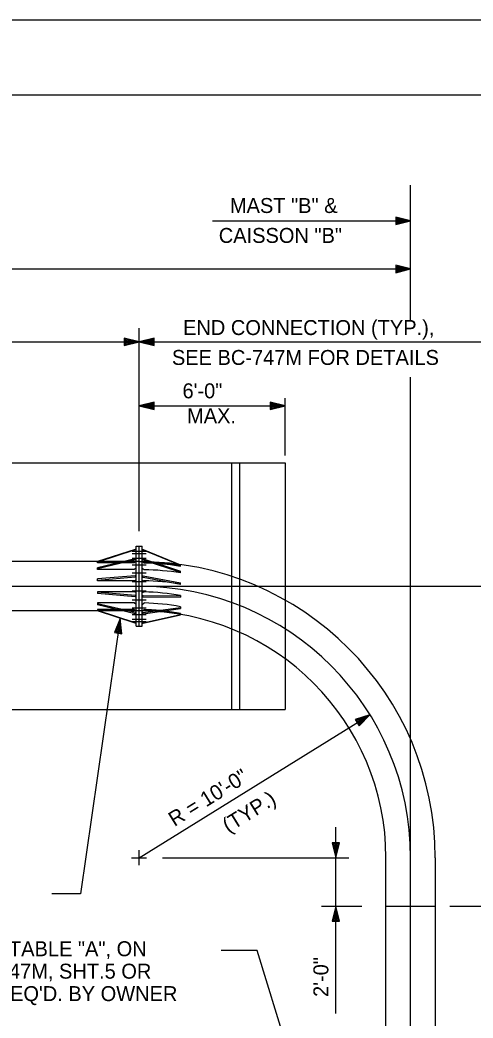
# Model space of a CAD drawing. Extents: x 640117 to 642655, y 297247 to 298435.
# Drawn here: x 641584 to 641674.8, y 298235.3 to 298435.5 of the extents above; entities that cross this region are included whole.
import ezdxf

# ---------------------------------------------------------------- set-up
doc = ezdxf.new("R2010")
doc.units = 0
for name, color, linetype in [('2', 7, 'Continuous'), ('48', 7, 'Continuous'), ('49', 7, 'Continuous'), ('50', 7, 'Continuous'), ('52', 7, 'Continuous'), ('53', 7, 'Continuous'), ('55', 7, 'Continuous'), ('PLT-BNDY', 7, 'Continuous')]:
    doc.layers.add(name, color=color, linetype=linetype)

msp = doc.modelspace()

# ---------------------------------------------------------------- linework, layer by layer
at = {"layer": '2'}
msp.add_line((640998.46, 298420.46), (641784.46, 298420.46), dxfattribs=at)
at = {"layer": '48'}
for p, q in [((641606.53, 298328.95), (641609.3, 298328.95)), ((641606.53, 298328.47), (641609.3, 298328.47)), ((641606.53, 298327.54), (641609.3, 298327.54)), ((641606.53, 298326.23), (641609.3, 298326.23)), ((641606.53, 298324.62), (641609.3, 298324.62)), ((641606.53, 298322.83), (641609.3, 298322.83)), ((641606.53, 298320.97), (641609.3, 298320.97)), ((641606.53, 298319.18), (641609.3, 298319.18)), ((641606.53, 298317.57), (641609.3, 298317.57)), ((641606.53, 298316.25), (641609.3, 298316.25)), ((641606.53, 298315.33), (641609.3, 298315.33)), ((641606.53, 298314.85), (641609.3, 298314.85))]:
    msp.add_line(p, q, dxfattribs=at)
at = {"layer": '49'}
for p, q in [((641573.28, 298346.63), (641637.17, 298346.63)), ((641626.4, 298346.63), (641626.4, 298297.16)), ((641628.05, 298346.63), (641628.05, 298297.16)), ((641637.17, 298346.63), (641637.17, 298297.16)), ((641573.28, 298297.16), (641637.17, 298297.16))]:
    msp.add_line(p, q, dxfattribs=at)
at = {"layer": '50'}
for p, q in [((641662.33, 298375.25), (641662.33, 298402.36)), ((641662.33, 298166.4), (641662.33, 298363.86)), ((641032.47, 298321.9), (641730.35, 298321.9))]:
    msp.add_line(p, q, dxfattribs=at)
msp.add_arc((641607.91, 298267.48), 54.42, 0, 90, dxfattribs=at)
at = {"layer": '52'}
for p, q in [((641622.6, 298395.18), (641662.33, 298395.18)), ((641286.35, 298385.52), (641662.33, 298385.52)), ((641662.33, 298385.52), (641659.33, 298386.27)), ((641659.33, 298386.27), (641659.33, 298384.77)), ((641659.33, 298384.77), (641662.33, 298385.52)), ((641661.6, 298385.52), (641659.51, 298386.04)), ((641659.51, 298386.04), (641659.51, 298385)), ((641659.51, 298385), (641661.6, 298385.52)), ((641660.86, 298385.52), (641659.68, 298385.81)), ((641659.68, 298385.81), (641659.68, 298385.22)), ((641659.68, 298385.22), (641660.86, 298385.52)), ((641659.75, 298385.43), (641660.13, 298385.52)), ((641660.13, 298385.52), (641659.77, 298385.61)), ((641607.91, 298332.93), (641607.91, 298373.65)), ((641607.91, 298370.91), (641604.91, 298371.66)), ((641604.91, 298371.66), (641604.91, 298370.16)), ((641604.91, 298370.16), (641607.91, 298370.91)), ((641607.18, 298370.91), (641605.09, 298371.44)), ((641605.09, 298371.44), (641605.09, 298370.39)), ((641605.09, 298370.39), (641607.18, 298370.91)), ((641606.45, 298370.91), (641605.27, 298371.21)), ((641605.27, 298371.21), (641605.27, 298370.62)), ((641605.27, 298370.62), (641606.45, 298370.91)), ((641605.34, 298370.82), (641605.71, 298370.91)), ((641605.71, 298370.91), (641605.36, 298371)), ((641610.91, 298371.66), (641607.91, 298370.91)), ((641607.91, 298370.91), (641610.91, 298370.16)), ((641610.73, 298371.44), (641608.64, 298370.91)), ((641608.64, 298370.91), (641610.73, 298370.39)), ((641610.56, 298371.21), (641609.38, 298370.91)), ((641609.38, 298370.91), (641610.56, 298370.62)), ((641610.49, 298371.01), (641610.11, 298370.91)), ((641610.11, 298370.91), (641610.47, 298370.82)), ((641610.56, 298370.62), (641610.56, 298371.21)), ((641610.73, 298370.39), (641610.73, 298371.44)), ((641610.91, 298370.16), (641610.91, 298371.66)), ((641610.91, 298358.84), (641607.91, 298358.09)), ((641610.91, 298357.34), (641610.91, 298358.84)), ((641637.17, 298358.09), (641634.17, 298358.84)), ((641634.17, 298358.84), (641634.17, 298357.34)), ((641637.17, 298348.13), (641637.17, 298359.59)), ((641607.91, 298358.09), (641637.17, 298358.09)), ((641607.91, 298358.09), (641610.91, 298357.34)), ((641610.73, 298358.61), (641608.64, 298358.09)), ((641608.64, 298358.09), (641610.73, 298357.57)), ((641610.56, 298358.39), (641609.38, 298358.09)), ((641609.38, 298358.09), (641610.56, 298357.8)), ((641610.49, 298358.18), (641610.11, 298358.09)), ((641610.11, 298358.09), (641610.47, 298358)), ((641610.56, 298357.8), (641610.56, 298358.39)), ((641610.73, 298357.57), (641610.73, 298358.61)), ((641634.17, 298357.34), (641637.17, 298358.09)), ((641636.44, 298358.09), (641634.35, 298358.61)), ((641634.35, 298358.61), (641634.35, 298357.57)), ((641634.35, 298357.57), (641636.44, 298358.09)), ((641635.71, 298358.09), (641634.53, 298358.39)), ((641634.53, 298358.39), (641634.53, 298357.8)), ((641634.53, 298357.8), (641635.71, 298358.09)), ((641634.6, 298358), (641634.97, 298358.09)), ((641634.97, 298358.09), (641634.62, 298358.18)), ((641604.15, 298315.46), (641602.98, 298312.6)), ((641604.04, 298314.74), (641603.23, 298312.74)), ((641604.26, 298312.59), (641604.04, 298314.74)), ((641604.46, 298312.38), (641604.15, 298315.46)), ((641603.23, 298312.74), (641604.26, 298312.59)), ((641603.94, 298314.01), (641603.48, 298312.88)), ((641603.48, 298312.88), (641604.06, 298312.8)), ((641603.83, 298313.28), (641603.69, 298312.94)), ((641603.87, 298312.9), (641603.83, 298313.28)), ((641604.06, 298312.8), (641603.94, 298314.01)), ((641602.98, 298312.6), (641604.46, 298312.38)), ((641607.91, 298267.48), (641654.18, 298296.12)), ((641654.18, 298296.12), (641651.24, 298295.18)), ((641651.24, 298295.18), (641652.03, 298293.9)), ((641653.56, 298295.73), (641651.51, 298295.08)), ((641651.51, 298295.08), (641652.06, 298294.19)), ((641652.94, 298295.35), (641651.78, 298294.98)), ((641651.78, 298294.98), (641652.09, 298294.47)), ((641652.31, 298294.96), (641651.96, 298294.85)), ((641652.03, 298293.9), (641654.18, 298296.12)), ((641652.04, 298294.68), (641652.31, 298294.96)), ((641652.06, 298294.19), (641653.56, 298295.73)), ((641652.09, 298294.47), (641652.94, 298295.35)), ((641647.34, 298236.23), (641647.34, 298273.61)), ((641607.91, 298265.98), (641607.91, 298268.98)), ((641646.59, 298270.48), (641647.34, 298267.48)), ((641648.09, 298270.48), (641646.59, 298270.48)), ((641646.82, 298270.3), (641647.34, 298268.21)), ((641647.86, 298270.3), (641646.82, 298270.3)), ((641647.04, 298270.12), (641647.34, 298268.94)), ((641647.63, 298270.12), (641647.04, 298270.12)), ((641647.25, 298270.05), (641647.34, 298269.68)), ((641647.34, 298267.48), (641648.09, 298270.48)), ((641647.34, 298268.21), (641647.86, 298270.3)), ((641647.34, 298268.94), (641647.63, 298270.12)), ((641647.34, 298269.68), (641647.43, 298270.03)), ((641606.41, 298267.48), (641609.41, 298267.48)), ((641612.58, 298267.48), (641649.96, 298267.48)), ((641644.44, 298257.73), (641652.58, 298257.73)), ((641647.34, 298257.73), (641646.59, 298254.73)), ((641647.34, 298256.99), (641646.82, 298254.9)), ((641647.34, 298257.73), (641647.34, 298257.73)), ((641648.09, 298254.73), (641647.34, 298257.73)), ((641647.86, 298254.9), (641647.34, 298256.99)), ((641670.15, 298257.73), (641684.65, 298257.73)), ((641646.59, 298254.73), (641648.09, 298254.73)), ((641646.82, 298254.9), (641647.86, 298254.9)), ((641647.34, 298256.26), (641647.04, 298255.08)), ((641647.04, 298255.08), (641647.63, 298255.08)), ((641647.34, 298255.53), (641647.25, 298255.17)), ((641647.63, 298255.08), (641647.34, 298256.26)), ((641647.43, 298255.15), (641647.34, 298255.53))]:
    msp.add_line(p, q, dxfattribs=at)
for points in [[(641286.35, 298370.91), (641676.82, 298370.91)], [(641604.15, 298315.46), (641596.16, 298260.2), (641590.45, 298260.2)], [(641637.51, 298229.5), (641631.55, 298248.87), (641624.35, 298248.87)]]:
    msp.add_lwpolyline(points, dxfattribs=at)
at = {"layer": '53'}
for p, q in [((641662.33, 298395.18), (641659.33, 298395.93)), ((641659.33, 298395.93), (641659.33, 298394.43)), ((641659.33, 298394.43), (641662.33, 298395.18)), ((641661.6, 298395.18), (641659.51, 298395.7)), ((641659.51, 298395.7), (641659.51, 298394.66)), ((641659.51, 298394.66), (641661.6, 298395.18)), ((641660.86, 298395.18), (641659.68, 298395.47)), ((641659.68, 298395.47), (641659.68, 298394.88)), ((641659.68, 298394.88), (641660.86, 298395.18)), ((641659.75, 298395.09), (641660.13, 298395.18)), ((641660.13, 298395.18), (641659.77, 298395.27))]:
    msp.add_line(p, q, dxfattribs=at)
at = {"layer": '55'}
for p, q in [((641607.1, 298329.3), (641599.58, 298326.84)), ((641607.1, 298329.22), (641599.58, 298326.76)), ((641607.3, 298329.3), (641607.1, 298329.3)), ((641607.3, 298329.22), (641607.1, 298329.22)), ((641607.3, 298329.92), (641608.52, 298329.92)), ((641607.3, 298313.87), (641607.3, 298329.92)), ((641607.91, 298313.87), (641607.91, 298329.92)), ((641608.52, 298313.87), (641608.52, 298329.92)), ((641608.52, 298329.3), (641608.72, 298329.3)), ((641608.52, 298329.22), (641608.72, 298329.22)), ((641608.72, 298329.3), (641616.24, 298326.19)), ((641608.72, 298329.22), (641616.24, 298326.11)), ((641607.91, 298326.84), (641573.28, 298326.84)), ((641607.1, 298327.39), (641599.58, 298325.59)), ((641607.1, 298327.18), (641599.58, 298325.38)), ((641599.58, 298326.57), (641599.58, 298326.84)), ((641599.58, 298326.77), (641607.3, 298326.77)), ((641607.3, 298326.96), (641606.9, 298326.57)), ((641607.3, 298327.39), (641607.1, 298327.39)), ((641607.3, 298327.18), (641607.1, 298327.18)), ((641608.52, 298327.39), (641608.72, 298327.39)), ((641608.52, 298327.18), (641608.72, 298327.18)), ((641608.52, 298326.96), (641608.93, 298326.57)), ((641608.72, 298327.39), (641616.24, 298324.92)), ((641608.72, 298327.18), (641616.24, 298324.71)), ((641603.65, 298326.57), (641599.58, 298326.57)), ((641599.58, 298325.24), (641599.58, 298325.59)), ((641606.9, 298325.24), (641599.58, 298325.24)), ((641606.9, 298326.57), (641603.65, 298326.57)), ((641607.3, 298325.52), (641606.9, 298325.24)), ((641608.52, 298325.52), (641608.93, 298325.24)), ((641608.93, 298326.57), (641612.17, 298326.57)), ((641612.17, 298326.57), (641616.24, 298325.91)), ((641616.24, 298325.91), (641616.24, 298326.19)), ((641616.24, 298324.57), (641616.24, 298324.92)), ((641607.1, 298324.02), (641599.58, 298323.36)), ((641607.1, 298323.72), (641599.58, 298323.06)), ((641599.58, 298323.01), (641599.58, 298323.36)), ((641606.9, 298323.01), (641599.58, 298323.01)), ((641607.3, 298323.12), (641606.9, 298323.01)), ((641607.3, 298324.02), (641607.1, 298324.02)), ((641607.3, 298323.72), (641607.1, 298323.72)), ((641608.52, 298324.02), (641608.72, 298324.02)), ((641608.52, 298323.72), (641608.72, 298323.72)), ((641608.52, 298323.12), (641608.93, 298323.01)), ((641608.72, 298324.02), (641616.24, 298322.61)), ((641608.72, 298323.72), (641616.24, 298322.31)), ((641599.58, 298320.78), (641599.58, 298320.44)), ((641606.9, 298320.78), (641599.58, 298320.78)), ((641607.1, 298320.07), (641599.58, 298320.73)), ((641607.3, 298320.68), (641606.9, 298320.78)), ((641608.52, 298320.68), (641608.93, 298320.78)), ((641616.24, 298322.26), (641616.24, 298322.61)), ((641607.1, 298319.78), (641599.58, 298320.44)), ((641607.3, 298320.07), (641607.1, 298320.07)), ((641607.3, 298319.78), (641607.1, 298319.78)), ((641608.52, 298320.07), (641608.72, 298320.07)), ((641608.52, 298319.78), (641608.72, 298319.78)), ((641608.72, 298320.07), (641616.24, 298320)), ((641608.72, 298319.78), (641616.24, 298319.7)), ((641616.24, 298320.05), (641616.24, 298319.7)), ((641607.91, 298316.95), (641573.28, 298316.95)), ((641599.58, 298318.56), (641599.58, 298318.2)), ((641606.9, 298318.56), (641599.58, 298318.56)), ((641607.1, 298316.62), (641599.58, 298318.41)), ((641607.1, 298316.4), (641599.58, 298318.2)), ((641599.58, 298317.23), (641599.58, 298316.95)), ((641603.65, 298317.23), (641599.58, 298317.23)), ((641607.1, 298314.58), (641599.58, 298317.03)), ((641599.58, 298317.02), (641607.3, 298317.02)), ((641607.1, 298314.5), (641599.58, 298316.95)), ((641606.9, 298317.23), (641603.65, 298317.23)), ((641607.3, 298318.27), (641606.9, 298318.56)), ((641607.3, 298316.84), (641606.9, 298317.23)), ((641608.52, 298318.27), (641608.93, 298318.56)), ((641608.52, 298316.84), (641608.93, 298317.23)), ((641608.72, 298316.62), (641616.24, 298317.64)), ((641608.72, 298316.4), (641616.24, 298317.43)), ((641616.24, 298317.79), (641616.24, 298317.43)), ((641607.3, 298316.62), (641607.1, 298316.62)), ((641607.3, 298316.4), (641607.1, 298316.4)), ((641608.52, 298316.62), (641608.72, 298316.62)), ((641608.52, 298316.4), (641608.72, 298316.4)), ((641608.72, 298314.58), (641616.24, 298316.24)), ((641608.72, 298314.5), (641616.24, 298316.16)), ((641616.24, 298316.43), (641616.24, 298316.16)), ((641607.3, 298314.58), (641607.1, 298314.58)), ((641607.3, 298314.5), (641607.1, 298314.5)), ((641607.3, 298313.87), (641608.52, 298313.87)), ((641608.52, 298314.58), (641608.72, 298314.58)), ((641608.52, 298314.5), (641608.72, 298314.5)), ((641657.38, 298225.12), (641657.38, 298267.48)), ((641667.28, 298225.12), (641667.28, 298267.48)), ((641657.38, 298257.73), (641667.28, 298257.73))]:
    msp.add_line(p, q, dxfattribs=at)
for centre, radius, start, end in [((641607.91, 298267.48), 59.36, 0, 90), ((641607.91, 298273.13), 53.64, 81.0656, 90), ((641607.91, 298273.13), 53.44, 81.031, 88.9106), ((641607.91, 298273.13), 52.11, 80.8, 88.8828), ((641607.91, 298273.13), 49.88, 80.3857, 88.833), ((641607.91, 298273.13), 47.65, 79.9312, 88.7783), ((641607.91, 298273.13), 43.89, 79.058, 90), ((641607.91, 298267.48), 49.47, 0, 90), ((641607.91, 298273.13), 45.43, 79.4324, 88.7185), ((641607.91, 298273.13), 44.1, 83.6558, 88.6798), ((641607.91, 298273.13), 44.1, 79.1097, 83.6558)]:
    msp.add_arc(centre, radius, start, end, dxfattribs=at)
at = {"layer": 'PLT-BNDY'}
msp.add_lwpolyline([(640958.46, 298435.46), (641799.46, 298435.46), (641799.46, 297841.46), (640958.46, 297841.46)], close=True, dxfattribs=at)

# ---------------------------------------------------------------- texts
at = {"layer": '2'}
for s, p in [('  END CONNECTION (TYP.),', (641614.49, 298372.28)), ('SEE BC-747M FOR DETAILS ', (641614.49, 298366.28)), ('SEE TABLE "A", ON', (641572.69, 298247.72)), ('BC-747M, SHT.5 OR', (641572.69, 298243.22)), ("AS REQ'D. BY OWNER", (641572.69, 298238.72))]:
    msp.add_text(s, height=3, dxfattribs=at).set_placement(p)
for s, rotation, p in [('R = 10\'-0"', 31.7534, (641614.99, 298273.62)), ('(TYP.)', 31.7534, (641625.79, 298272.37)), ('2\'-0"', 90, (641645.84, 298239.55))]:
    msp.add_text(s, height=3, rotation=rotation, dxfattribs=at).set_placement(p)
at = {"layer": '52'}
msp.add_text('6\'-0"', height=3, dxfattribs=at).set_placement((641616.61, 298359.59))
at = {"layer": '53'}
for s, p in [('  MAST "B" &', (641623.88, 298396.75)), ('CAISSON "B"', (641623.88, 298390.75)), ('MAX.', (641617.52, 298354.59))]:
    msp.add_text(s, height=3, dxfattribs=at).set_placement(p)

doc.saveas('drawing.dxf')
